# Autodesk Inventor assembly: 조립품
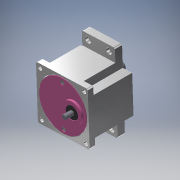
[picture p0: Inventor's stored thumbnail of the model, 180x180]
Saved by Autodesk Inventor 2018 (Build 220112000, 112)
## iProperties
Created: 2020-07
Part Number: 조립품
Material: 일반
Document SubType Name: Assembly
Designer: Admin
Author: Admin
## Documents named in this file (10)
- C:\Users\Admin\Desktop\700707V1002\조립품.iam
- C:\Users\Admin\Desktop\700707V1002\본체.ipt
- C:\Users\Admin\Desktop\700707V1002\커버.ipt
- C:\Users\Admin\Desktop\700707V1002\베어링 608.ipt
- C:\Users\Admin\Desktop\700707V1002\베어링 6003.ipt
- C:\Users\Admin\Desktop\700707V1002\메인 축.ipt
- C:\Users\Admin\Desktop\700707V1002\서브 축.ipt
- C:\Users\Admin\Desktop\700707V1002\볼트 M4.ipt
- C:\Users\Admin\Desktop\700707V1002\오일 실 8 22 7.ipt
- C:\Users\Admin\Desktop\700707V1002\오일 실 17 32 8.ipt
